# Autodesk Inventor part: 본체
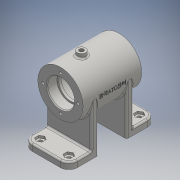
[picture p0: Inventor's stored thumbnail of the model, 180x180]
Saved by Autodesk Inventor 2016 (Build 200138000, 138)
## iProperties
Created: 2017-02
Part Number: 본체
Material: 일반
Document SubType Name: Modeling
Designer: USER
Density: 1 g/cm^3
Appearance: 기본값
Author: USER
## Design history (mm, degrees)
sketch "스케치1"
  geometry: L1 (0, 0)-(54, 0); L2 (54, 0)-(54, -35); L3 (54, -35)-(0, -35); L4 (0, -35)-(0, 0); L5 (0, -69)-(54, -69); L6 (54, -69)-(54, -104); L7 (54, -104)-(0, -104); L8 (0, -104)-(0, -69)
  constraints: 16 end point, 4 parallel, 2 horizontal, 2 perpendicular, 2 point on line
  dimensions: "d0" = 54 distance of L1.start L1.end; "d1" = 35 distance between parallel lines of L3 L1; "d3" = 104 distance between parallel lines of L7 L1; "d4" = 35 distance between parallel lines of L7 L5
extrude "돌출1" new body sketch "스케치1" distance "d5" = 8; taper "d6" = 0 deg
fillet "모깎기1" dims "d7" = 10
fillet "모깎기2" dims "d8" = 10
sketch "스케치2"
  geometry: L1 (0, -35)-(54, -35) reference; L2 (10, -4.804)-(14.5, -7.402); L3 (14.5, -7.402)-(14.5, -12.598); L4 (14.5, -12.598)-(10, -15.196); L5 (10, -15.196)-(5.5, -12.598); L6 (5.5, -12.598)-(5.5, -7.402); L7 (5.5, -7.402)-(10, -4.804); L8 (44, -4.804)-(48.5, -7.402); L9 (48.5, -7.402)-(48.5, -12.598); L10 (48.5, -12.598)-(44, -15.196); L11 (44, -15.196)-(39.5, -12.598); L12 (39.5, -12.598)-(39.5, -7.402); L13 (39.5, -7.402)-(44, -4.804); L14 (0, -10)-(0, -35) reference; L15 (54, -35)-(54, -10) reference; L16 (44, 0)-(10, 0) reference; C1 r 4.5 at (10, -10); C2 r 4.5 at (44, -10); A1 r 10 centre (10, -10) between (10, 0) and (0, -10) reference; A2 r 10 centre (44, -10) between (54, -10) and (44, 0) reference; 5 further points
  constraints: 24 end point, 2 centre point, 2 coincident, 2 midpoint, 2 tangent, 26 other
  dimensions: "d12" = 9 diameter of C1; "d13" = 9 diameter of C2
extrude "돌출2" cut sketch "스케치2" distance "d14" = 3; taper "d15" = 0 deg
sketch "스케치3"
  geometry: L1 (54, -69)-(0, -69) reference; L2 (10, -88.804)-(14.5, -91.402); L3 (14.5, -91.402)-(14.5, -96.598); L4 (14.5, -96.598)-(10, -99.196); L5 (10, -99.196)-(5.5, -96.598); L6 (5.5, -96.598)-(5.5, -91.402); L7 (5.5, -91.402)-(10, -88.804); L8 (44, -88.804)-(48.5, -91.402); L9 (48.5, -91.402)-(48.5, -96.598); L10 (48.5, -96.598)-(44, -99.196); L11 (44, -99.196)-(39.5, -96.598); L12 (39.5, -96.598)-(39.5, -91.402); L13 (39.5, -91.402)-(44, -88.804); L14 (54, -94)-(54, -69) reference; L15 (0, -69)-(0, -94) reference; L16 (10, -104)-(44, -104) reference; C1 r 4.5 at (10, -94); C2 r 4.5 at (44, -94); A1 r 10 centre (44, -94) between (44, -104) and (54, -94) reference; A2 r 10 centre (10, -94) between (0, -94) and (10, -104) reference; 5 further points
  constraints: 24 end point, 2 centre point, 2 coincident, 2 midpoint, 2 tangent, 26 other
  dimensions: "d16" = 9 diameter of C1; "d17" = 9 diameter of C2
extrude "돌출3" cut sketch "스케치3" distance "d18" = 3; taper "d19" = 0 deg
sketch "스케치4"
  geometry: L1 (-44, -104)-(-10, -104) reference; L2 (0, -94)-(0, -69) reference; L3 (0, -69)-(-54, -69) reference; L4 (-54, -69)-(-54, -94) reference; C1 r 2.5 at (-10, -94); C2 r 2.5 at (-44, -94); A1 r 10 centre (-44, -94) between (-54, -94) and (-44, -104) reference; A2 r 10 centre (-10, -94) between (-10, -104) and (0, -94) reference; 1 further point
  constraints: 2 centre point, 2 coincident
  dimensions: "d20" = 5 diameter of C1; "d21" = 5 diameter of C2
extrude "돌출4" cut sketch "스케치4" stored distance "d22" = 3; taper "d23" = 0 deg
sketch "스케치5"
  geometry: L1 (-10, 0)-(-44, 0) reference; L2 (-54, -10)-(-54, -35) reference; L3 (-54, -35)-(0, -35) reference; L4 (0, -35)-(0, -10) reference; C1 r 2.5 at (-10, -10); C2 r 2.5 at (-44, -10); A1 r 10 centre (-10, -10) between (0, -10) and (-10, 0) reference; A2 r 10 centre (-44, -10) between (-44, 0) and (-54, -10) reference; 1 further point
  constraints: 2 centre point, 2 coincident
  dimensions: "d24" = 5 diameter of C1; "d25" = 5 diameter of C2
extrude "돌출5" cut sketch "스케치5" stored distance "d26" = 3; taper "d27" = 0 deg
node "작업 평면1"
sketch "스케치6"
  geometry: L1 (54, 0)-(0, 0) reference; C1 r 27 at (27, 60); 1 further point
  constraints: 1 centre point, 1 midpoint, 1 vertical alignment
  dimensions: "d28" = 54 diameter of C1; "d29" = 60 distance from line of L1 C1.centre
extrude "돌출6" join sketch "스케치6" stored distance "d30" = 70; taper "d31" = 0 deg
sketch "스케치7"
  geometry: C1 r 27 at (0, 0) reference; C2 r 16 at (0, 0); 1 further point
  constraints: 1 centre point, 1 coincident
  dimensions: "d32" = 32 diameter of C2
extrude "돌출7" cut sketch "스케치7" distance "d33" = 12; taper "d34" = 0 deg
sketch "스케치8"
  geometry: C1 r 16 at (0, 0) reference; C2 r 14 at (0, 0); 1 further point
  constraints: 1 centre point, 1 coincident
  dimensions: "d35" = 28 diameter of C2
extrude "돌출8" cut sketch "스케치8" distance "d36" = 3; taper "d37" = 0 deg
fillet "모깎기4" dims "d38" = 0.3
chamfer "모따기1" distance "d39" = 1; stored, may be unused: second distance "d40" = 2, angle "d41" = 45 deg
sketch "스케치9"
  geometry: C1 r 14 at (0, 0) reference; C2 r 22 at (0, 0); 1 further point
  constraints: 1 centre point, 1 coincident
  dimensions: "d42" = 44 diameter of C2
extrude "돌출9" cut sketch "스케치9" distance "d43" = 40; taper "d44" = 0 deg
fillet "모깎기5" dims "d45" = 3
sketch "스케치10"
  geometry: C1 r 27 at (0, 0) reference; C2 r 16 at (0, 0); 1 further point
  constraints: 1 centre point, 1 coincident
  dimensions: "d46" = 32 diameter of C2
extrude "돌출10" cut sketch "스케치10" distance "d47" = 12; taper "d48" = 0 deg
chamfer "모따기2" distance "d49" = 1; stored, may be unused: second distance "d50" = 2, angle "d51" = 45 deg
fillet "모깎기6" dims "d52" = 0.3
sketch "스케치11"
  geometry: C1 r 15.7 at (0, 0) reference; C2 r 14 at (0, 0); 1 further point
  constraints: 1 centre point, 1 coincident
  dimensions: "d53" = 28 diameter of C2
extrude "돌출11" cut sketch "스케치11" distance "d54" = 3; taper "d55" = 0 deg
sketch "스케치12"
  geometry: L1 (0, -69)-(54, -69) reference; L2 (0, -69)-(54, -69); L3 (54, -69)-(54, -77); L4 (54, -77)-(0, -77); L5 (0, -77)-(0, -69); L6 (54, -35)-(0, -35) reference; L7 (0, -35)-(54, -35); L8 (54, -35)-(54, -27); L9 (54, -27)-(0, -27); L10 (0, -27)-(0, -35); 5 further points
  constraints: 16 end point, 4 midpoint, 4 parallel, 4 point on line, 2 horizontal, 2 perpendicular, 2 vertical alignment
  dimensions: "d56" = 8 distance of L4.end L2.start; "d57" = 8 distance of L9.end L7.start; "d58" = 54 distance between parallel lines of L3 L5
extrude "돌출12" join sketch "스케치12" stored distance "d59" = 3; taper "d60" = 0 deg
fillet "모깎기7" dims "d61" = 2
fillet "모깎기8" dims "d62" = 2
fillet "모깎기9" dims "d63" = 2
sketch "스케치13"
  geometry: C1 r 27 at (0, 0) reference; C2 r 17 at (0, 0) reference; A1 r 21 centre (0, 0) between (0, 21) and (-21, 0); 3 further points
  constraints: 4 point on circle, 2 horizontal alignment, 2 vertical alignment, 1 centre point, 1 coincident
  dimensions: "d64" = 42 diameter of A1
hole "구멍1" sketch "스케치13" at (0, 21), (-21, 0), (0, -21), (21, 0) diameter "d65" = 3.242; stored, may be unused: countersink angle "d69" = 90 deg, drill point angle "d71" = 118 deg; dims "d66" = 8, "d67" = 4, "d68" = 2, "d70" = 10
node "작업 평면3"
sketch "스케치14"
  geometry: L1 (-17, -52)-(17, -52) reference; L2 (-27, -35)-(27, -35) reference; C1 r 5 at (0, -10); 2 further points
  constraints: 1 centre point, 1 midpoint, 1 vertical alignment
  dimensions: "d73" = 10 diameter of C1; "d74" = 25 distance from line of L2 C1.centre
extrude "돌출13" join sketch "스케치14" stored distance "d75" = 3; taper "d76" = 0 deg
fillet "모깎기10" dims "d77" = 2
sketch "스케치18"
  geometry: C1 r 5 at (0, 0) reference; 1 further point
  constraints: 1 coincident
hole "구멍3" sketch "스케치18" at (0, 0) diameter "d85" = 5.188; stored, may be unused: countersink angle "d89" = 90 deg, drill point angle "d91" = 0 deg; dims "d86" = 12, "d87" = 4, "d88" = 2, "d90" = 16
node "작업 평면5"
sketch "스케치20"
  geometry: L1 (0, 0)-(-16.339, -25.16); L2 (0, 0)-(0, -14); 2 further points
  constraints: 4 end point, 1 coincident, 1 vertical, 1 vertical alignment, 1 other
  dimensions: "d92" = 30 distance of L1.start L1.end; "d109" = 33 deg angle of L2 L1
node "작업 평면7"
sketch "스케치23"
  geometry: L1 (23, 0)-(19, 0) reference; L2 (35, 27)-(-35, 27) reference; L3 (-35, 27)-(-35, -27) reference; 4 further points
  constraints: 1 midpoint, 1 other
  dimensions: "d105" = 27 distance from line of L2 point (0, 0); "d106" = 35 distance from line of L3 point (0, 0)
feature "엠보싱1" sketch "스케치23" dims "d107" = 0.5, "d108" = 0
node "작업 평면8"
sketch "스케치24"
  geometry: C1 r 6 at (0, 0); 2 further points
  constraints: 1 centre point, 1 coincident
  dimensions: "d110" = 12 diameter of C1
extrude "돌출15" join sketch "스케치24" stored distance "d111" = 10; taper "d112" = 0 deg
fillet "모깎기12" dims "d113" = 2
sketch "스케치25"
  geometry: C1 r 6 at (0, 0) reference; 2 further points
  constraints: 1 coincident
hole "구멍5" sketch "스케치25" at (0, 0) diameter "d114" = 5.188; stored, may be unused: countersink angle "d118" = 90 deg, drill point angle "d120" = 0 deg; dims "d115" = 12, "d116" = 4, "d117" = 2, "d119" = 16
node "솔리드1"
mirror "대칭1"
node "투영된 루프1"
node "투영된 루프2"
node "투영된 루프3"
node "투영된 루프4"
node "투영된 루프5"
node "투영된 루프6"
node "투영된 루프7"
node "투영된 루프8"
node "투영된 루프9"
node "투영된 루프10"
node "투영된 루프12"
node "투영된 루프14"
